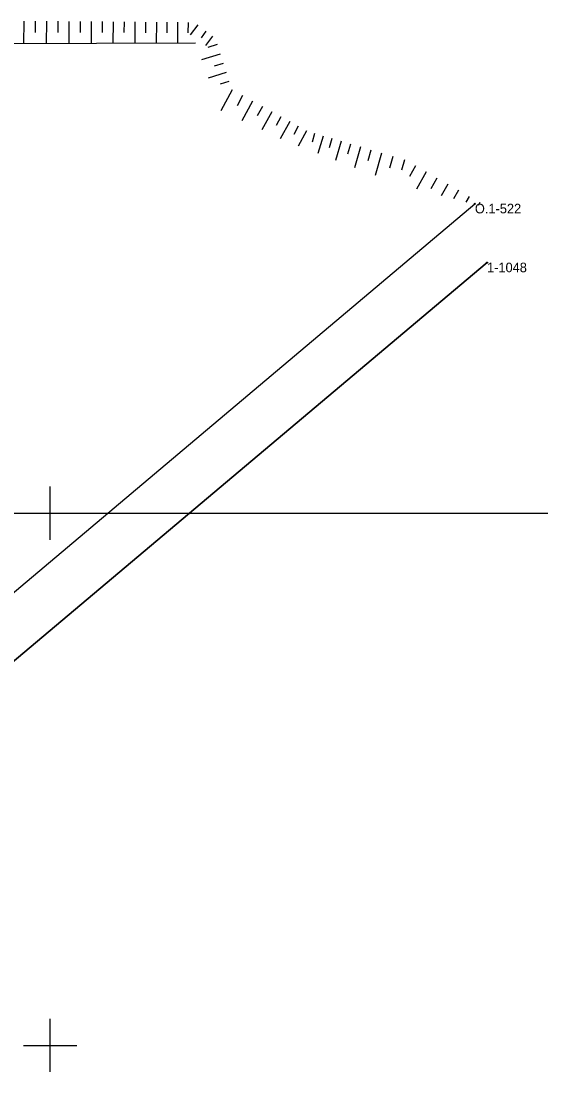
# Model space of a CAD drawing. Extents: x 5598798 to 5599616, y 5661498 to 5662453.
# Drawn here: x 5599247.3 to 5599296.1, y 5661947.5 to 5662046.2 of the extents above; entities that cross this region are included whole.
import ezdxf

# ---------------------------------------------------------------- set-up
doc = ezdxf.new("R2010")
doc.units = 0
for name, color, linetype in [('BUBZ_L_1', 7, 'Continuous'), ('Dzialki', 7, 'Continuous'), ('Kontury', 7, 'Continuous'), ('Numery_punktow', 7, 'Continuous'), ('Podzial_sekcyjny_krzyze', 7, 'Continuous'), ('Podzial_sekcyjny_podstawowy', 7, 'Continuous'), ('Punkty', 7, 'Continuous'), ('Uzytki', 7, 'Continuous')]:
    doc.layers.add(name, color=color, linetype=linetype)

# ---------------------------------------------------------------- blocks, each defined once
blk = doc.blocks.new('GRO')
blk.add_circle((0, 0), 0.045)

msp = doc.modelspace()

# ---------------------------------------------------------------- linework, layer by layer
at = {"layer": 'BUBZ_L_1'}
for p, q in [((5599247.510033, 5662046.217782), (5599247.492748, 5662044.074416)), ((5599248.581717, 5662046.20914), (5599248.573124, 5662045.143633)), ((5599249.647223, 5662046.200547), (5599249.630137, 5662044.081815)), ((5599250.706589, 5662046.192004), (5599250.698095, 5662045.138743)), ((5599251.759849, 5662046.18351), (5599251.742959, 5662044.08913)), ((5599252.807039, 5662046.175065), (5599252.798643, 5662045.13391)), ((5599253.848194, 5662046.166668), (5599253.831498, 5662044.09636)), ((5599254.883348, 5662046.15832), (5599254.875048, 5662045.129132)), ((5599255.912536, 5662046.150021), (5599255.896032, 5662044.103508)), ((5599256.935792, 5662046.141769), (5599256.927588, 5662045.12441)), ((5599257.953151, 5662046.133564), (5599257.936837, 5662044.110573)), ((5599258.964647, 5662046.125407), (5599258.956537, 5662045.119741)), ((5599259.970313, 5662046.117297), (5599259.954186, 5662044.117557)), ((5599260.970183, 5662046.109234), (5599260.962166, 5662045.115126)), ((5599261.96429, 5662046.101217), (5599261.948349, 5662044.124461)), ((5599262.952668, 5662046.093246), (5599262.94474, 5662045.110176)), ((5599263.854805, 5662045.849066), (5599263.137044, 5662044.90884)), ((5599264.636235, 5662045.25253), (5599264.169162, 5662044.640691)), ((5599265.248074, 5662044.785457), (5599264.579059, 5662043.909085)), ((5599263.665708, 5662044.130407), (5599241.337013, 5662044.053104)), ((5599265.702515, 5662044.010919), (5599264.806239, 5662043.730237)), ((5599265.983197, 5662043.114643), (5599264.226669, 5662042.56456)), ((5599266.527706, 5662041.375916), (5599264.841658, 5662040.847904)), ((5599266.258239, 5662042.236379), (5599265.397775, 5662041.966912)), ((5599266.791711, 5662040.532892), (5599265.965773, 5662040.274237)), ((5599267.097387, 5662039.745409), (5599266.021433, 5662037.790967)), ((5599268.074608, 5662039.207432), (5599267.554111, 5662038.261963)), ((5599269.020077, 5662038.686935), (5599268.012907, 5662036.857436)), ((5599269.934827, 5662038.18335), (5599269.447604, 5662037.298322)), ((5599270.819855, 5662037.696127), (5599269.87707, 5662035.983584)), ((5599271.676126, 5662037.224735), (5599271.22005, 5662036.396285)), ((5599272.504576, 5662036.768659), (5599271.622062, 5662035.165595)), ((5599273.306108, 5662036.327402), (5599272.883871, 5662035.560419)), ((5599274.073091, 5662035.905165), (5599273.286721, 5662034.476745)), ((5599274.84355, 5662035.647326), (5599274.611098, 5662034.85248)), ((5599275.638397, 5662035.414873), (5599275.154394, 5662033.75988)), ((5599276.465893, 5662035.172872), (5599276.213951, 5662034.311383)), ((5599277.327382, 5662034.92093), (5599276.8028, 5662033.127175)), ((5599278.22426, 5662034.658639), (5599277.951194, 5662033.724919)), ((5599279.157979, 5662034.385573), (5599278.589413, 5662032.441423)), ((5599280.130054, 5662034.10129), (5599279.834093, 5662033.089284)), ((5599281.14206, 5662033.805329), (5599280.525823, 5662031.698175)), ((5599282.195637, 5662033.497211), (5599281.874862, 5662032.400355)), ((5599283.292493, 5662033.176436), (5599283.012849, 5662032.220223)), ((5599284.331112, 5662032.615761), (5599283.757102, 5662031.608288)), ((5599285.338584, 5662032.04175), (5599284.409189, 5662030.410526)), ((5599286.346056, 5662031.46774), (5599285.772046, 5662030.460268)), ((5599287.353529, 5662030.89373), (5599286.733507, 5662029.805502)), ((5599288.361001, 5662030.31972), (5599287.895667, 5662029.50299)), ((5599289.368473, 5662029.74571), (5599289.057826, 5662029.200478)), ((5599290.375945, 5662029.171699), (5599290.219985, 5662028.897966)), ((5599291.383417, 5662028.597689), (5599291.382144, 5662028.595454))]:
    msp.add_line(p, q, dxfattribs=at)
at = {"layer": 'Dzialki'}
for p, q in [((5599207.78, 5661959.89), (5599289.91, 5662029.05)), ((5599207.13, 5661952.92), (5599291.05, 5662023.52))]:
    msp.add_line(p, q, dxfattribs=at)
at = {"layer": 'Kontury'}
for p, q in [((5599207.78, 5661959.89), (5599289.91, 5662029.05)), ((5599291.05, 5662023.52), (5599207.13, 5661952.92))]:
    msp.add_line(p, q, dxfattribs=at)
at = {"layer": 'Podzial_sekcyjny_krzyze'}
for p, q in [((5599250, 5661997.5), (5599250, 5662002.5)), ((5599247.5, 5662000), (5599252.5, 5662000)), ((5599250, 5661947.5), (5599250, 5661952.5)), ((5599247.5, 5661950), (5599252.5, 5661950))]:
    msp.add_line(p, q, dxfattribs=at)
at = {"layer": 'Podzial_sekcyjny_podstawowy'}
msp.add_line((5599200, 5662000), (5599600, 5662000), dxfattribs=at)
at = {"layer": 'Uzytki'}
for p, q in [((5599207.78, 5661959.89), (5599289.91, 5662029.05)), ((5599291.05, 5662023.52), (5599207.13, 5661952.92))]:
    msp.add_line(p, q, dxfattribs=at)

# ---------------------------------------------------------------- block references
at = {"layer": 'Punkty'}
for p in [(5599289.91, 5662029.05), (5599291.05, 5662023.52)]:
    msp.add_blockref('GRO', p, dxfattribs=at)

# ---------------------------------------------------------------- texts
at = {"layer": 'Numery_punktow'}
for s, p in [('O.1-522', (5599289.91, 5662028.15)), ('1-1048', (5599291.05, 5662022.62))]:
    msp.add_text(s, height=0.9, dxfattribs=at).set_placement(p)

doc.saveas('drawing.dxf')
